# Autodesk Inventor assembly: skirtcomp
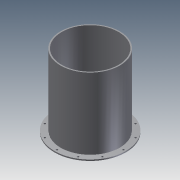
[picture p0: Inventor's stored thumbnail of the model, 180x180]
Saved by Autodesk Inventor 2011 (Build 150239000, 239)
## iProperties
Created: 2010-07
Part Number: skirtcomp
Document SubType Name: Assembly
Designer: mklassen
OD: 24.000 in
THK: 0.500 in
LEN: 3.000 ft
SVOFS: 6.000 in
SKLEN: 2.500 ft
SKFWDT: 3.000 in
SKFTHK: 0.500 in
Author: mklassen
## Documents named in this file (3)
- O:\cadd\tutorials\inventor 2011\iLogic\skirtcomp.iam
- O:\cadd\tutorials\inventor 2011\iLogic\SkirtFlange-02.ipt
- O:\cadd\tutorials\inventor 2011\iLogic\Skirt-02.ipt
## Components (2 placed, 2 different names)
1. SkirtFlange-02:1
2. Skirt-02:1
